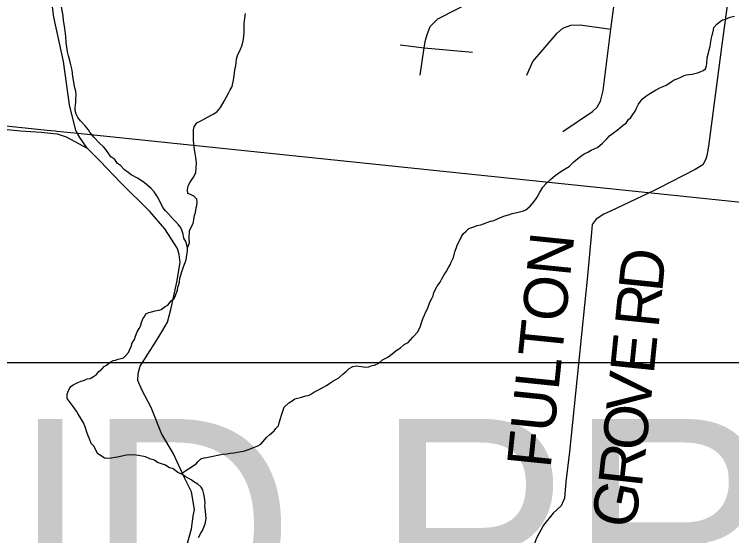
# Model space of a CAD drawing. Extents: x 0 to 34, y 0 to 22.
# Drawn here: x 6.0237 to 6.4878, y 14.9414 to 15.2785 of the extents above; entities that cross this region are included whole.
import ezdxf

# ---------------------------------------------------------------- set-up
doc = ezdxf.new("R2010")
doc.units = 0
for name, color, linetype in [('Default', 7, 'Continuous'), ('GM_X_Corporation', 7, 'Continuous'), ('GM_X_County_Road', 7, 'Continuous'), ('GM_X_County_Road_Text', 7, 'Continuous'), ('GM_X_Minor_River', 7, 'Continuous'), ('GM_X_Township', 7, 'Continuous'), ('GM_X_Township_Road', 7, 'Continuous'), ('SH_Text', 7, 'Continuous')]:
    doc.layers.add(name, color=color, linetype=linetype)

msp = doc.modelspace()

# ---------------------------------------------------------------- linework, layer by layer
at = {"layer": 'Default'}
msp.add_lwpolyline([(5.72003, 15.05333), (7.10043, 15.05333), (7.10043, 14.62233), (5.72003, 14.62233)], close=True, dxfattribs=at)
at = {"layer": 'GM_X_Corporation'}
msp.add_lwpolyline([(6.59355, 15.14652), (6.43382, 15.16308), (6.06467, 15.20137), (6.05118, 15.20277), (6.05019, 15.20287), (6.04707, 15.20319), (6.00558, 15.2075), (5.85494, 15.22312), (5.63104, 15.24634), (5.61401, 15.10982), (5.60301, 15.02173), (5.5402, 14.5449)], dxfattribs=at)
at = {"layer": 'GM_X_County_Road'}
for points in [[(6.51023, 15.47964), (6.50588, 15.44325), (6.49596, 15.36557), (6.48127, 15.25721), (6.47288, 15.19325), (6.47221, 15.18966), (6.47177, 15.1872), (6.47114, 15.18494), (6.46914, 15.18119), (6.46406, 15.1782), (6.44065, 15.16601), (6.43771, 15.16461)], [(6.06803, 15.196), (6.0661, 15.19878), (6.06479, 15.20111), (6.06345, 15.20349), (6.05924, 15.21991), (6.05539, 15.24804), (6.04915, 15.27666), (6.04731, 15.29196), (6.04683, 15.30167), (6.04879, 15.30737), (6.05483, 15.32333), (6.05738, 15.33738), (6.0569, 15.35048), (6.0538, 15.36715), (6.05002, 15.37935), (6.04928, 15.38955), (6.04966, 15.39669), (6.05071, 15.40277), (6.05166, 15.41124), (6.05419, 15.42379), (6.05676, 15.43265), (6.06046, 15.44302), (6.06491, 15.45557), (6.06805, 15.46316)], [(6.13563, 14.93651), (6.13818, 14.94581), (6.13927, 14.95407), (6.14012, 14.95842), (6.1383, 14.96975), (6.13377, 14.97881), (6.12656, 14.99439), (6.11895, 15.00748), (6.11227, 15.02437), (6.10625, 15.03528), (6.10353, 15.0418), (6.10382, 15.04616), (6.10506, 15.05107), (6.11505, 15.06663), (6.11976, 15.07433), (6.12271, 15.07939), (6.12497, 15.0877), (6.12875, 15.10529), (6.13098, 15.11808), (6.13039, 15.12326), (6.12927, 15.12709), (6.12103, 15.13975), (6.11131, 15.15111), (6.09234, 15.16966), (6.07916, 15.1836), (6.07078, 15.19203), (6.06803, 15.196)], [(6.43771, 15.16461), (6.43393, 15.16282), (6.41724, 15.15489), (6.40943, 15.15127), (6.40516, 15.14939), (6.4001, 15.14599), (6.39759, 15.14266), (6.39714, 15.13746), (6.39453, 15.10947), (6.38275, 14.99571), (6.38043, 14.97618), (6.37964, 14.96576), (6.37747, 14.96077), (6.37226, 14.95593), (6.36609, 14.94824), (6.36149, 14.93981), (6.35953, 14.93467), (6.35652, 14.93121), (6.35341, 14.92844), (6.34781, 14.92526), (6.33747, 14.9207), (6.32175, 14.9139)]]:
    msp.add_lwpolyline(points, dxfattribs=at)
at = {"layer": 'GM_X_Minor_River'}
for points in [[(6.09995, 15.06602), (6.10132, 15.06828), (6.10211, 15.07036), (6.10311, 15.07319), (6.10448, 15.07526), (6.10527, 15.07696), (6.10588, 15.07923), (6.10687, 15.08168), (6.10804, 15.08337), (6.10882, 15.08488), (6.11073, 15.08561), (6.11245, 15.08615), (6.11474, 15.08668), (6.11722, 15.0872), (6.11875, 15.08775), (6.12126, 15.0896), (6.12298, 15.09052), (6.12512, 15.09315), (6.12685, 15.09445), (6.12764, 15.09615), (6.12843, 15.09803), (6.12923, 15.10011), (6.12945, 15.10201), (6.13005, 15.10371), (6.13046, 15.10541), (6.13069, 15.10788), (6.13129, 15.10977), (6.13209, 15.11222), (6.13289, 15.11449), (6.13369, 15.11695), (6.13468, 15.11921), (6.13509, 15.12111), (6.13531, 15.123), (6.13573, 15.12547), (6.13558, 15.12775), (6.13451, 15.13157), (6.13341, 15.13387), (6.13288, 15.13635), (6.13197, 15.13884), (6.13124, 15.14094), (6.12994, 15.14249), (6.12807, 15.14442), (6.12657, 15.14578), (6.12489, 15.14771), (6.12303, 15.15002), (6.12153, 15.15138), (6.11967, 15.1535), (6.11765, 15.1581), (6.11618, 15.16059), (6.11414, 15.16367), (6.11208, 15.16599), (6.10946, 15.16832), (6.10759, 15.16987), (6.10326, 15.17261), (6.09931, 15.17477), (6.09724, 15.17613), (6.09498, 15.17788), (6.09237, 15.18078), (6.0903, 15.18215), (6.08864, 15.18465), (6.086, 15.1864), (6.0847, 15.18833), (6.08285, 15.19121), (6.08136, 15.19276), (6.07874, 15.19527), (6.07519, 15.19914), (6.07258, 15.20222), (6.07166, 15.20376), (6.06942, 15.20646), (6.06643, 15.20956), (6.06476, 15.21186), (6.06366, 15.21398), (6.06293, 15.21627), (6.06296, 15.21798), (6.06318, 15.21969), (6.06341, 15.22177), (6.06345, 15.22405), (6.06367, 15.22633), (6.06352, 15.2288), (6.0628, 15.23091), (6.06246, 15.23319), (6.06193, 15.23586), (6.06159, 15.23834), (6.06109, 15.24234), (6.0602, 15.24578), (6.05948, 15.24864), (6.05878, 15.2517), (6.05806, 15.25418), (6.05754, 15.25723), (6.05721, 15.26028), (6.05689, 15.26408), (6.05673, 15.26599), (6.05622, 15.26942), (6.05606, 15.27094), (6.05572, 15.27323), (6.05555, 15.27475), (6.05522, 15.27761), (6.05417, 15.28333)], [(6.1356, 15.1275), (6.13697, 15.13077), (6.13682, 15.13362), (6.13691, 15.13875), (6.13927, 15.14327), (6.13988, 15.14592), (6.14031, 15.14858), (6.14091, 15.15047), (6.14134, 15.15331), (6.14174, 15.15482), (6.14197, 15.15729), (6.14162, 15.15901), (6.13975, 15.16094), (6.13768, 15.16193), (6.13598, 15.16272), (6.13564, 15.16501), (6.13606, 15.16766), (6.13743, 15.16992), (6.1388, 15.17198), (6.13977, 15.17349), (6.14115, 15.17613), (6.14139, 15.17935), (6.14144, 15.1822), (6.14129, 15.18449), (6.14112, 15.18601), (6.14059, 15.18849), (6.14043, 15.19001), (6.14009, 15.1923), (6.13975, 15.19459), (6.1396, 15.19725), (6.13967, 15.20143), (6.13952, 15.2039), (6.13993, 15.2058), (6.14169, 15.20824), (6.14437, 15.20971), (6.14668, 15.211), (6.15108, 15.21321), (6.15281, 15.21413), (6.15493, 15.21561), (6.15706, 15.21823), (6.15941, 15.22237), (6.16236, 15.22802), (6.16334, 15.22972), (6.16451, 15.23179), (6.16553, 15.23595), (6.16618, 15.2405), (6.16641, 15.24278), (6.16702, 15.24524), (6.16747, 15.2496), (6.16808, 15.25187), (6.17005, 15.25602), (6.17104, 15.25847), (6.17187, 15.26226), (6.1721, 15.26473), (6.17231, 15.26624), (6.17235, 15.26871), (6.17238, 15.27043), (6.17242, 15.27252), (6.17286, 15.27593), (6.17329, 15.27896)], [(6.34103, 15.14811), (6.34333, 15.14883), (6.34581, 15.14974), (6.34868, 15.15045), (6.35307, 15.15151), (6.3546, 15.15206), (6.3573, 15.15448), (6.36001, 15.15747), (6.36196, 15.16029), (6.36334, 15.16312), (6.36568, 15.16669), (6.36781, 15.16912), (6.37051, 15.17174), (6.3736, 15.17434), (6.37783, 15.17731), (6.38013, 15.1786), (6.38263, 15.18008), (6.38572, 15.18307), (6.38939, 15.18623), (6.39227, 15.18827), (6.39476, 15.18937), (6.39687, 15.19066), (6.39879, 15.19158), (6.4009, 15.19249), (6.40417, 15.19529), (6.40727, 15.19827), (6.40882, 15.19996), (6.41132, 15.20181), (6.41363, 15.20367), (6.41632, 15.20572), (6.41787, 15.20702), (6.41941, 15.20813), (6.42077, 15.2102), (6.42251, 15.21188), (6.42387, 15.21376), (6.42524, 15.21583), (6.42622, 15.2179), (6.42741, 15.22035), (6.42857, 15.22185), (6.42993, 15.22373), (6.43225, 15.22559), (6.43532, 15.22762), (6.43839, 15.22947), (6.44127, 15.23094), (6.44338, 15.23185), (6.44529, 15.23277), (6.44702, 15.23388), (6.44856, 15.2348), (6.45067, 15.2361), (6.45258, 15.23682), (6.4545, 15.23774), (6.45699, 15.23903), (6.45852, 15.23938), (6.46023, 15.23954), (6.46214, 15.23989), (6.46576, 15.24059), (6.46749, 15.24132), (6.4694, 15.24223), (6.47094, 15.24335), (6.47154, 15.24524), (6.47176, 15.24694), (6.47201, 15.25036), (6.47282, 15.25358), (6.47324, 15.25547), (6.47384, 15.25774), (6.47406, 15.25945), (6.4747, 15.26324), (6.47511, 15.26494), (6.47551, 15.26645), (6.47612, 15.26853), (6.47633, 15.27005), (6.47827, 15.27211), (6.48039, 15.27378), (6.48193, 15.27489), (6.48384, 15.27543), (6.4869, 15.27671), (6.48957, 15.27723)], [(6.13134, 14.98148), (6.14122, 14.98793), (6.14257, 14.98943), (6.14431, 14.99111), (6.14641, 14.99164), (6.14794, 14.992), (6.15118, 14.99251), (6.155, 14.99339), (6.15843, 14.99409), (6.16109, 14.99424), (6.16338, 14.99477), (6.16567, 14.99492), (6.16796, 14.99545), (6.17273, 14.99632), (6.17693, 14.99776), (6.17846, 14.99831), (6.18076, 14.99922), (6.18306, 15.00051), (6.18694, 15.005), (6.18887, 15.00687), (6.19176, 15.00929), (6.19293, 15.01079), (6.19467, 15.01247), (6.19508, 15.01437), (6.19589, 15.0172), (6.19649, 15.01928), (6.19829, 15.02439), (6.20119, 15.02719), (6.20349, 15.02867), (6.20522, 15.02978), (6.20694, 15.03032), (6.20885, 15.03066), (6.21229, 15.03175), (6.21439, 15.03228), (6.21593, 15.0332), (6.21784, 15.03431), (6.22034, 15.0356), (6.22322, 15.03726), (6.22552, 15.03855), (6.22783, 15.04003), (6.22975, 15.04132), (6.23359, 15.04354), (6.23648, 15.04615), (6.23841, 15.04764), (6.24034, 15.0495), (6.24264, 15.05079), (6.24493, 15.05113), (6.24645, 15.05111), (6.251, 15.05046), (6.25291, 15.05062), (6.2552, 15.05134), (6.25673, 15.05169), (6.25941, 15.05297), (6.26191, 15.05502), (6.26498, 15.05668), (6.2671, 15.05816), (6.26941, 15.06002), (6.27134, 15.06151), (6.27345, 15.0628), (6.27577, 15.06504), (6.27845, 15.06633), (6.28155, 15.0697), (6.28465, 15.07325), (6.28642, 15.07683), (6.28683, 15.07835), (6.28802, 15.08156), (6.28882, 15.08364), (6.29, 15.08609), (6.29078, 15.08759), (6.29178, 15.09043), (6.29257, 15.09231), (6.29376, 15.09476), (6.29454, 15.09646), (6.29515, 15.09854), (6.29712, 15.10269), (6.29907, 15.10532), (6.30024, 15.10758), (6.302, 15.1104), (6.30298, 15.11209), (6.30455, 15.11472), (6.30553, 15.11661), (6.30632, 15.11831), (6.30789, 15.12132), (6.3083, 15.12321), (6.30871, 15.12492), (6.30971, 15.12775), (6.31011, 15.12926), (6.31148, 15.13171), (6.31306, 15.13491), (6.31423, 15.13679), (6.31597, 15.13829), (6.31771, 15.13997), (6.32038, 15.14087), (6.32306, 15.14196), (6.32554, 15.14249), (6.32726, 15.14303), (6.33166, 15.14466), (6.33319, 15.14502), (6.33491, 15.14556), (6.33721, 15.14666), (6.34103, 15.14811)], [(6.14289, 14.94018), (6.14427, 14.94301), (6.14544, 14.9447), (6.14623, 14.94697), (6.14703, 14.94905), (6.14763, 14.95113), (6.14766, 14.95265), (6.1475, 14.95474), (6.14736, 14.95741), (6.14701, 14.95893), (6.14684, 14.96046), (6.14707, 14.96273), (6.14691, 14.96464), (6.14675, 14.96616), (6.14604, 14.96922), (6.1455, 14.97094), (6.14457, 14.97266), (6.14233, 14.97479), (6.13988, 14.97617), (6.138, 14.97753), (6.13574, 14.97871), (6.13424, 14.97969), (6.13236, 14.98105), (6.12953, 14.98224), (6.12634, 14.98458), (6.12369, 14.98558), (6.12143, 14.98695), (6.11822, 14.98814), (6.11633, 14.98875), (6.11427, 14.9903), (6.11124, 14.99112), (6.1086, 14.9923), (6.10405, 14.99314), (6.10216, 14.99356), (6.0993, 14.99361), (6.09626, 14.99347), (6.09321, 14.99276), (6.09035, 14.99224), (6.08882, 14.99189), (6.08653, 14.99155), (6.08368, 14.99122), (6.08197, 14.99144), (6.07991, 14.99299), (6.07765, 14.99436), (6.07672, 14.9959), (6.07526, 14.99916), (6.07339, 15.00109), (6.0723, 15.00396), (6.07138, 15.00588), (6.07066, 15.00836), (6.06958, 15.01181), (6.06848, 15.0143), (6.067, 15.0166), (6.06589, 15.01871), (6.06478, 15.02044), (6.06385, 15.02198), (6.06181, 15.02487), (6.05977, 15.02757), (6.05791, 15.03007), (6.05776, 15.03273), (6.05817, 15.03425), (6.05915, 15.03613), (6.06013, 15.03782), (6.06167, 15.03894), (6.06473, 15.04041), (6.06684, 15.04132), (6.06894, 15.04185), (6.07067, 15.04277), (6.07276, 15.04312), (6.07488, 15.04441), (6.0768, 15.04571), (6.07835, 15.04758), (6.08028, 15.04907), (6.08183, 15.05075), (6.08336, 15.05168), (6.08606, 15.05372), (6.08759, 15.05464), (6.08912, 15.05481), (6.09084, 15.05554), (6.09275, 15.05588), (6.09428, 15.05643), (6.09582, 15.05792), (6.09756, 15.05979), (6.09816, 15.0613), (6.09934, 15.06375), (6.09995, 15.06602)]]:
    msp.add_lwpolyline(points, dxfattribs=at)
at = {"layer": 'GM_X_Township'}
msp.add_lwpolyline([(6.59355, 15.14652), (6.43382, 15.16308), (6.06467, 15.20137), (6.05118, 15.20277), (6.05019, 15.20287), (6.04707, 15.20319), (6.00558, 15.2075), (5.85494, 15.22312), (5.63104, 15.24634), (5.64509, 15.35895), (5.64565, 15.3634), (5.64639, 15.36938), (5.65308, 15.42302), (5.66745, 15.53814), (5.69239, 15.73807), (5.72112, 15.95514), (5.75974, 16.24674)], dxfattribs=at)
at = {"layer": 'GM_X_Township_Road'}
for p, q in [((6.27322, 15.25885), (6.28887, 15.25689)), ((6.28887, 15.25689), (6.32003, 15.25404))]:
    msp.add_line(p, q, dxfattribs=at)
for points in [[(6.37856, 15.20273), (6.39768, 15.21561), (6.40077, 15.21841), (6.40288, 15.22244), (6.4047, 15.22922), (6.40954, 15.26892), (6.41378, 15.29972), (6.41647, 15.31946), (6.42045, 15.35131), (6.42377, 15.37675), (6.42529, 15.38846)], [(6.28618, 15.23914), (6.28887, 15.25689), (6.28962, 15.26188), (6.29083, 15.26547), (6.2927, 15.27061), (6.29764, 15.27556), (6.31, 15.28191), (6.32968, 15.2922), (6.33635, 15.29579), (6.34671, 15.30132), (6.35518, 15.3052), (6.36059, 15.30661), (6.36588, 15.30661), (6.37294, 15.30615), (6.38177, 15.30497), (6.41378, 15.29972)], [(6.35534, 15.23924), (6.35911, 15.24808), (6.36462, 15.25415), (6.37497, 15.26625), (6.37859, 15.2695), (6.38367, 15.27142), (6.38977, 15.27174), (6.40954, 15.26892)], [(6.00559, 15.20527), (6.0276, 15.20327), (6.04104, 15.2024), (6.04505, 15.20191), (6.04905, 15.20153), (6.05143, 15.20128), (6.05717, 15.19923), (6.07078, 15.19203)]]:
    msp.add_lwpolyline(points, dxfattribs=at)

# ---------------------------------------------------------------- texts
at = {"layer": 'GM_X_County_Road_Text'}
for s, height, rotation, p in [('FULTON', 0.028409, 84.1528, (6.37057, 14.98448)), ('D', 0.02841, 84.1321, (6.44274, 15.09838)), ('R', 0.02841, 84.1511, (6.44036, 15.07517)), ('E', 0.02841, 84.1549, (6.43731, 15.04533)), ('V', 0.02841, 84.1536, (6.43476, 15.02046)), ('O', 0.02841, 84.0802, (6.43218, 14.99555)), ('R', 0.02841, 83.6751, (6.42959, 14.97214)), ('G', 0.02841, 78.1271, (6.42397, 14.94471))]:
    msp.add_text(s, height=height, rotation=rotation, dxfattribs=at).set_placement(p)
at = {"layer": 'SH_Text'}
msp.add_text('END PROJECT', height=0.1399997, dxfattribs=at).set_placement((5.80995, 14.87687))

doc.saveas('drawing.dxf')
